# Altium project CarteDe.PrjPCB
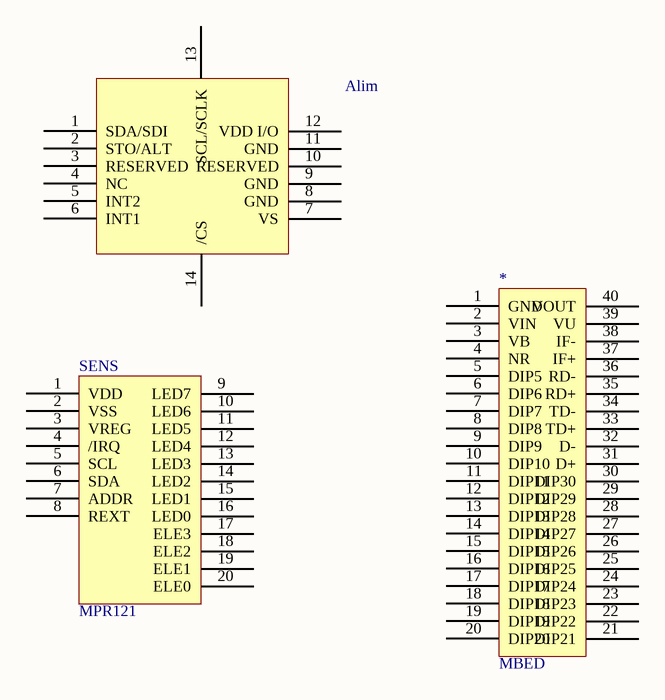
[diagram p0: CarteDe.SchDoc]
1 sheet, 3 parts. Net scope: global (net labels, ports and power ports of the same name join across sheets).
Board file: CarteDe.PcbDoc

## Sheet CarteDe.SchDoc
size A4

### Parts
*  MBED  [LCC40]
Alim  ADXL345  [LCC14]  (value not drawn)
SENS  MPR121  [LCC20]

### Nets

Not connected (* = marked no-connect by the designer): * 1(GND) 2(VIN) 3(VB) 4(NR) 5(DIP5) 6(DIP6) 7(DIP7) 8(DIP8) 9(DIP9) 10(DIP10) 11(DIP11) 12(DIP12) 13(DIP13) 14(DIP14) 15(DIP15) 16(DIP16) 17(DIP17) 18(DIP18) 19(DIP19) 20(DIP20) 21(DIP21) 22(DIP22) 23(DIP23) 24(DIP24) 25(DIP25) 26(DIP26) 27(DIP27) 28(DIP28) 29(DIP29) 30(DIP30) 31(D+) 32(D-) 33(TD+) 34(TD-) 35(RD+) 36(RD-) 37(IF+) 38(IF-) 39(VU) 40(VOUT); Alim 1(SDA/SDI) 2(STO/ALT) 3(RESERVED) 4(NC) 5(INT2) 6(INT1) 7(VS) 8(GND) 9(GND) 10(RESERVED) 11(GND) 12(VDD_I/O) 13(SCL/SCLK) 14(/CS); SENS 1(VDD) 2(VSS) 3(VREG) 4(/IRQ) 5(SCL) 6(SDA) 7(ADDR) 8(REXT) 9(LED7) 10(LED6) 11(LED5) 12(LED4) 13(LED3) 14(LED2) 15(LED1) 16(LED0) 17(ELE3) 18(ELE2) 19(ELE1) 20(ELE0)

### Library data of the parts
Alim = ADXL345: Alimentation ADXL345
SENS = MPR121: Touch sensor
